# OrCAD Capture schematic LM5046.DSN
size Custom; title: LM5046 Simulation Example; company: Phoenix Design Center, National Semiconductor; note: Model by Eric Lee, Phoenix Design Center , National Semiconductor
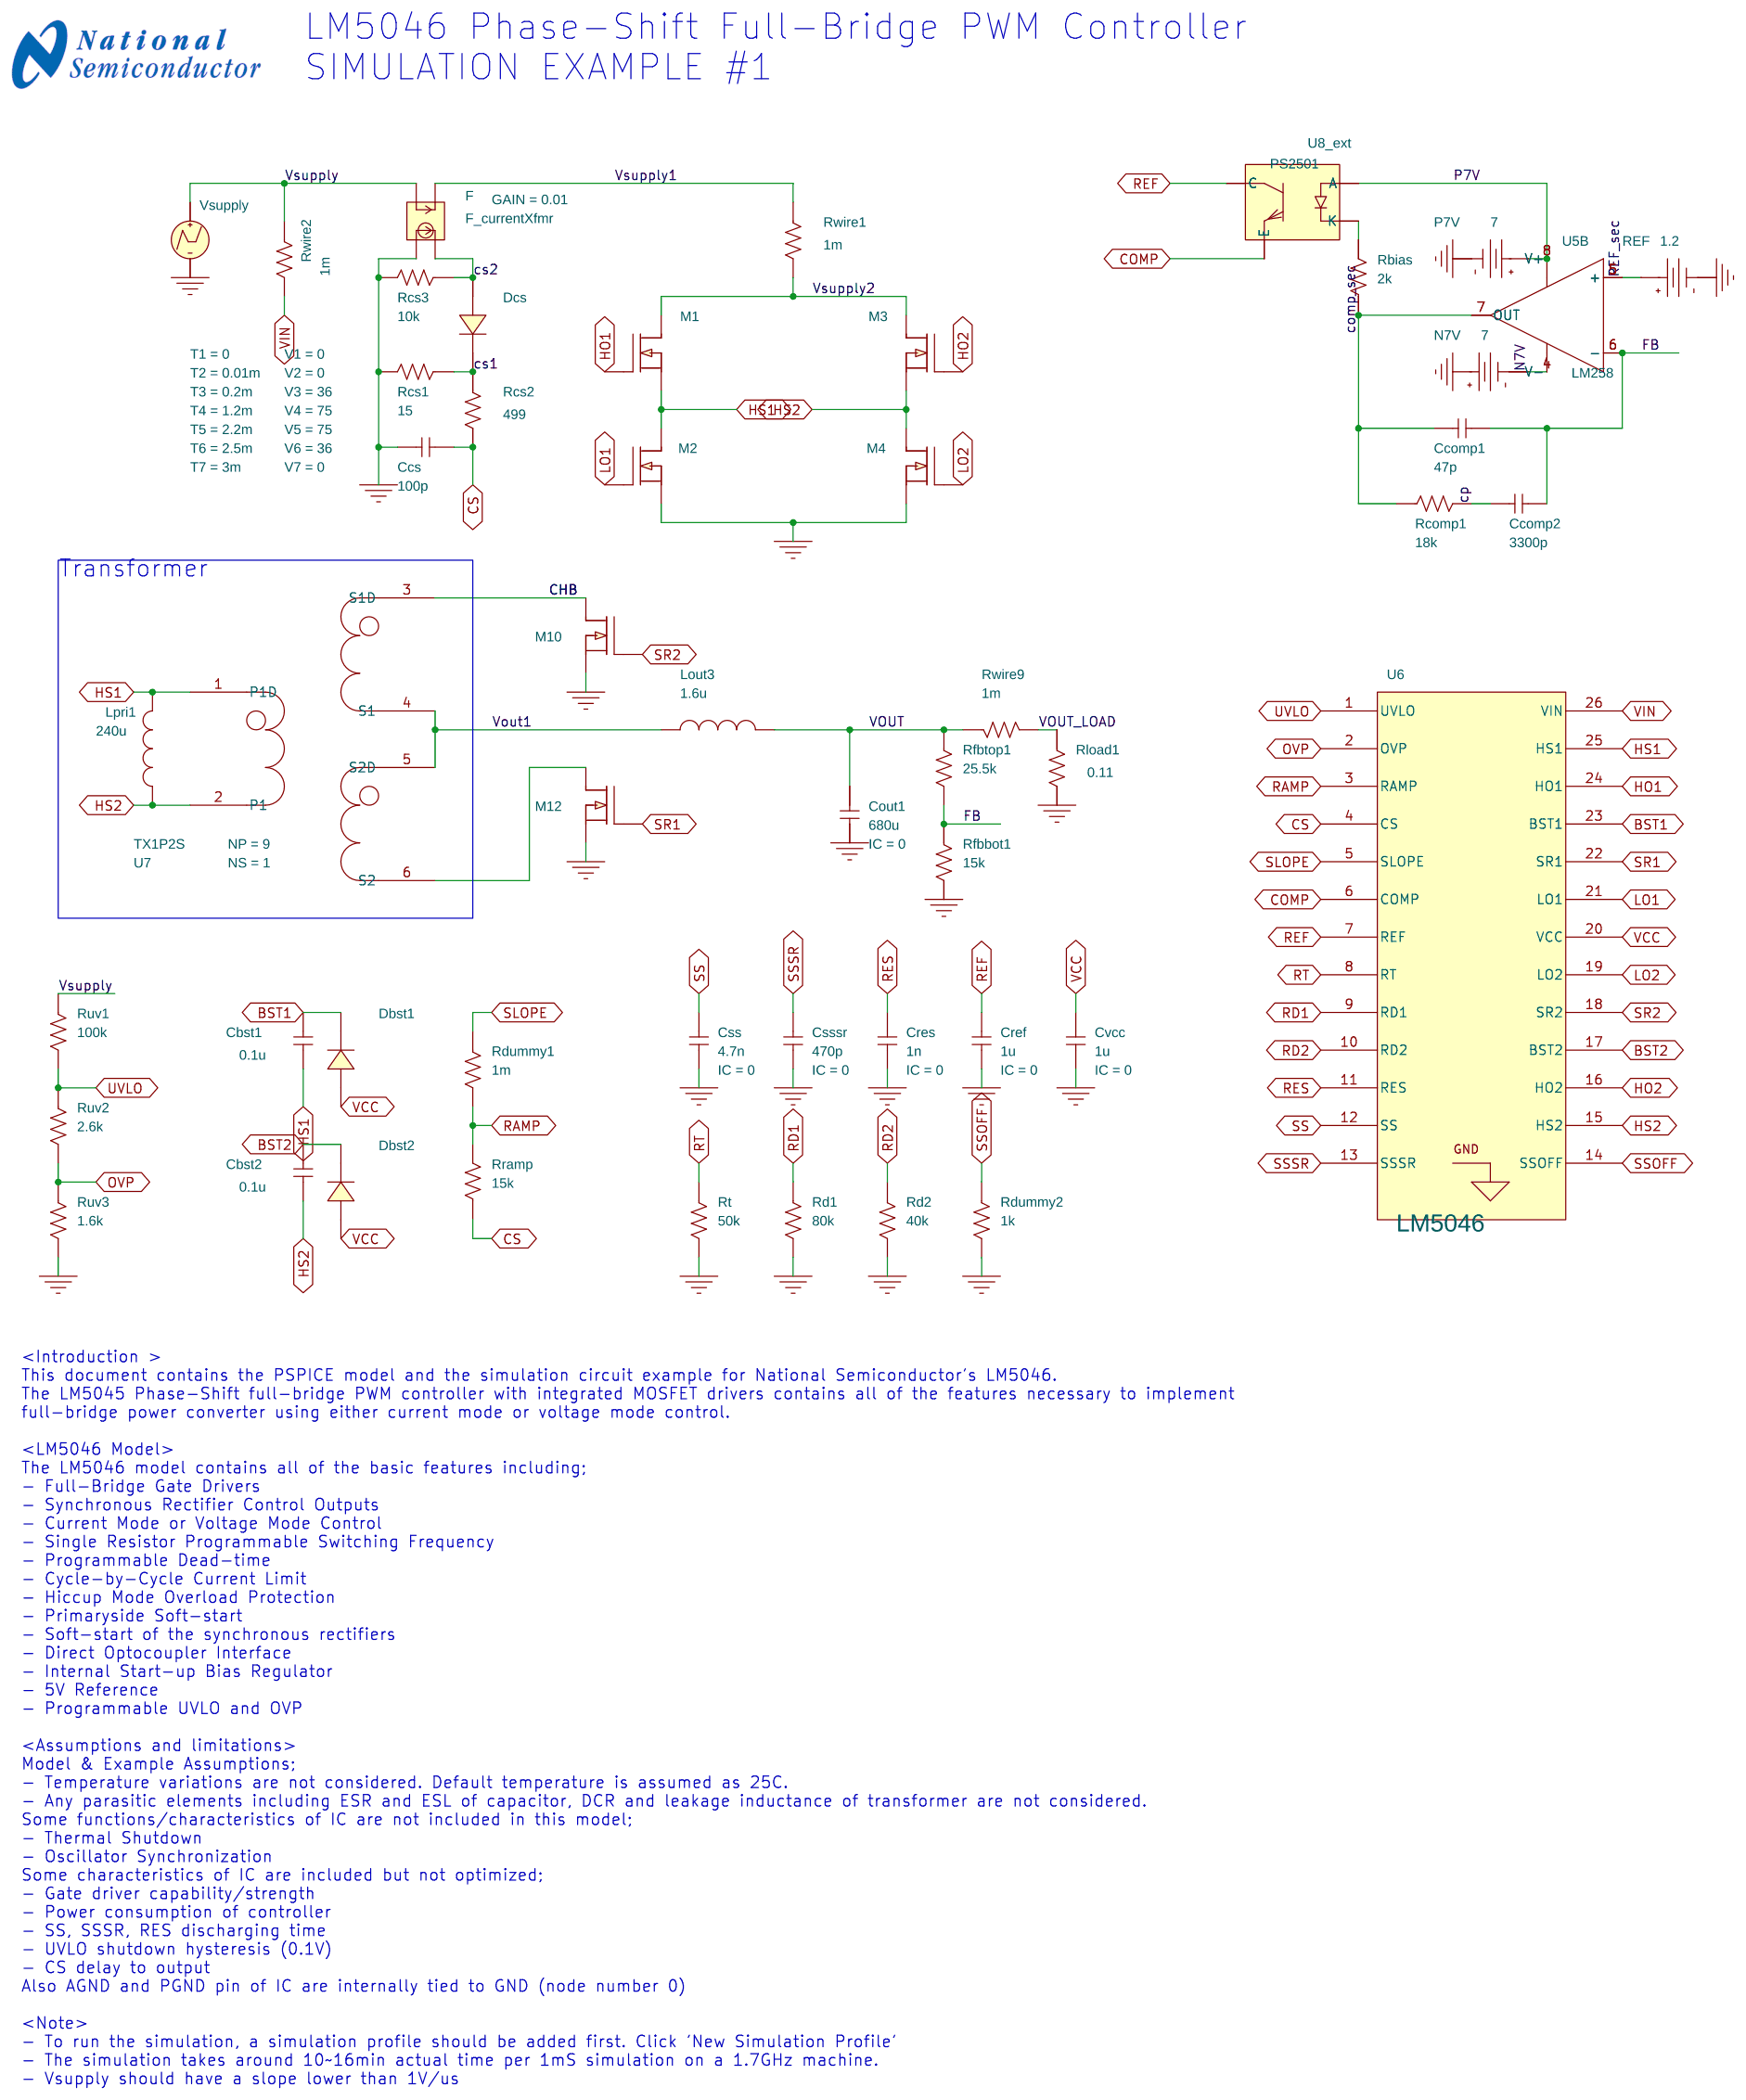
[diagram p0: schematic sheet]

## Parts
Cbst1  0.1u  [RAD/CK05]
Cbst2  0.1u  [RAD/CK05]
Ccomp1  47p  [RAD/CK05]
Ccomp2  3300p  [RAD/CK05]
Ccs  100p  [RAD/CK05]
Cout1  680u  [RAD/CK05]
Cref  1u  [RAD/CK05]
Cres  1n  [RAD/CK05]
Css  4.7n  [RAD/CK05]
Csssr  470p  [RAD/CK05]
Cvcc  1u  [RAD/CK05]
Dbst1  DNOM
Dbst2  DNOM
Dcs  DNOM
F_currentXfmr  F
Lout3  1.6u  [DISC/.350x.175/LS.200x.100/.034]
Lpri1  240u  [DISC/.350x.175/LS.200x.100/.034]
M1  NMOSNOM
M2  NMOSNOM
M3  NMOSNOM
M4  NMOSNOM
M10  NMOSNOM
M12  NMOSNOM
N7V  VDC
P7V  VDC
Rbias  2k  [AX/RC05]
Rcomp1  18k  [AX/RC05]
Rcs1  15  [AX/RC05]
Rcs2  499  [AX/RC05]
Rcs3  10k  [AX/RC05]
Rd1  80k  [AX/RC05]
Rd2  40k  [AX/RC05]
Rdummy1  1m  [AX/RC05]
Rdummy2  1k  [AX/RC05]
REF  VDC
Rfbbot1  15k  [AX/RC05]
Rfbtop1  25.5k  [AX/RC05]
Rload1  0.11  [AX/RC05]
Rramp  15k  [AX/RC05]
Rt  50k  [AX/RC05]
Ruv1  100k  [AX/RC05]
Ruv2  2.6k  [AX/RC05]
Ruv3  1.6k  [AX/RC05]
Rwire1  1m  [AX/RC05]
Rwire2  1m  [AX/RC05]
Rwire9  1m  [AX/RC05]
U5  LM258  [DIP.100/8/W.300/L.450]  (section B)
U6  LM5046
U7  TX1P2S
U8_ext  PS2501  [DIP4]
Vsupply  VPWL

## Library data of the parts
Cbst1 Cbst2 Ccomp1 Ccomp2 Ccs = C: IC: 0
Cout1 = C_2: IC: 0
Cref Cres Css Csssr Cvcc = C_3: IC: 0
Dbst1 Dbst2 Dcs = DNOM
F_currentXfmr = F: GAIN: 0.01
Lout3 Lpri1 = L
M1-M4 M10 M12 = NMOSNOM
N7V P7V = VDC: DC: 7
Rbias Rcomp1 Rcs1-Rcs3 Rd1 Rd2 Rdummy1 Rdummy2 Rfbbot1 Rfbtop1 Rload1 Rramp Rt Ruv1-Ruv3 Rwire1 Rwire2 Rwire9 = R
REF = VDC: DC: 1.2
U5 = LM258
U6 = LM5046
U7 = TX1P2S: NP: 9; NS: 1
U8_ext = PS2501-1
Vsupply = VPWL: PSpiceTemplate: V^@REFDES %+ %- ?DC|DC @DC| ?AC|AC @AC|\n+PWL @T1 @V1 @T2 @V2 #T3/@T3 @V3/ #T4/@T4 @V4/ #T5/@T5 @V5/ #T6/@T6 @V6/ #T7/@T7 @V7/ #T8/@T8 @V8/ #T9/@T9 @V9/ #T10/@T10 @V10/; T1: 0; T2: 0.01m; T3: 0.2m; T4: 1.2m; T5: 2.2m; T6: 2.5m; T7: 3m; V1: 0; V2: 0; V3: 36; V4: 75; V5: 75; V6: 36; V7: 0

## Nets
P7V: P7V.0(+) U5.8(V+) U8_ext.1(A)
VCC: Cvcc.1 Dbst1.2(A) Dbst2.2(A) U6.20(VCC)
VIN: Rwire2.2 U6.26(VIN)
0: Ccs.2 Cout1.2 Cref.2 Cres.2 Css.2 Csssr.2 Cvcc.2 F_currentXfmr.3 M2.1(s) M4.1(s) M10.1(s) M12.1(s) N7V.0(+) P7V.1(-) Rcs1.2 Rcs3.2 Rd1.2 Rd2.2 Rdummy2.2 REF.1(-) Rfbbot1.2 Rload1.2 Rt.2 Ruv3.2 Vsupply.2(-)
BST1: Cbst1.2 Dbst1.1(C) U6.23(BST1)
BST2: Cbst2.2 Dbst2.1(C) U6.17(BST2)
CHB: M10.2(d) U7.3(S1D)
COMP: U6.6(COMP) U8_ext.3(E)
comp_sec: Ccomp1.2 Rbias.1 Rcomp1.1 U5.7(OUT)
cp: Ccomp2.2 Rcomp1.2
CS: Ccs.1 Rcs2.2 Rramp.1 U6.4(CS)
cs1: Dcs.1(C) Rcs1.1 Rcs2.1
cs2: Dcs.2(A) F_currentXfmr.4 Rcs3.1
FB: Ccomp1.1 Ccomp2.1 Rfbbot1.1 Rfbtop1.2 U5.6(-)
HO1: M1.3(g) U6.24(HO1)
HO2: M3.3(g) U6.16(HO2)
HS1: Cbst1.1 Lpri1.1 M1.1(s) M2.2(d) U6.25(HS1) U7.1(P1D)
HS2: Cbst2.1 Lpri1.2 M3.1(s) M4.2(d) U6.15(HS2) U7.2(P1)
LO1: M2.3(g) U6.21(LO1)
LO2: M4.3(g) U6.19(LO2)
N7V: N7V.1(-) U5.4(V-)
OVP: Ruv2.2 Ruv3.1 U6.2(OVP)
RAMP: Rdummy1.2 Rramp.2 U6.3(RAMP)
RD1: Rd1.1 U6.9(RD1)
RD2: Rd2.1 U6.10(RD2)
REF: Cref.1 U6.7(REF) U8_ext.4(C)
REF_sec: REF.0(+) U5.5(+)
RES: Cres.1 U6.11(RES)
RT: Rt.1 U6.8(RT)
SLOPE: Rdummy1.1 U6.5(SLOPE)
SR1: M12.3(g) U6.22(SR1)
SR2: M10.3(g) U6.18(SR2)
SS: Css.1 U6.12(SS)
SSOFF: Rdummy2.1 U6.14(SSOFF)
SSSR: Csssr.1 U6.13(SSSR)
UVLO: Ruv1.2 Ruv2.1 U6.1(UVLO)
VOUT: Cout1.1 Lout3.2 Rfbtop1.1 Rwire9.1
Vout1: Lout3.1 U7.4(S1) U7.5(S2D)
VOUT_LOAD: Rload1.1 Rwire9.2
Vsupply: F_currentXfmr.1 Ruv1.1 Rwire2.1 Vsupply.1(+)
Vsupply1: F_currentXfmr.2 Rwire1.1
Vsupply2: M1.2(d) M3.2(d) Rwire1.2
N16934950: Rbias.2 U8_ext.2(K)
N16942154: M12.2(d) U7.6(S2)

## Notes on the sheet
- LM5046 Phase-Shift Full-Bridge PWM Controller
  SIMULATION EXAMPLE #1
- Transformer
- <Introduction >
  This document contains the PSPICE model and the simulation circuit example for National Semiconductor's LM5046.
  The LM5045 Phase-Shift full-bridge PWM controller with integrated MOSFET drivers contains all of the features necessary to implement
  full-bridge power converter using either current mode or voltage mode control.
  <LM5046 Model>
  The LM5046 model contains all of the basic features including;
  - Full-Bridge Gate Drivers
  - Synchronous Rectifier Control Outputs
  - Current Mode or Voltage Mode Control
  - Single Resistor Programmable Switching Frequency
  - Programmable Dead-time
  - Cycle-by-Cycle Current Limit
  - Hiccup Mode Overload Protection
  - Primaryside Soft-start
  - Soft-start of the synchronous rectifiers
  - Direct Optocoupler Interface
  - Internal Start-up Bias Regulator
  - 5V Reference
  - Programmable UVLO and OVP
  <Assumptions and limitations>
  Model & Example Assumptions;
  - Temperature variations are not considered. Default temperature is assumed as 25C.
  - Any parasitic elements including ESR and ESL of capacitor, DCR and leakage inductance of transformer are not considered.
  Some functions/characteristics of IC are not included in this model;
  - Thermal Shutdown
  - Oscillator Synchronization
  Some characteristics of IC are included but not optimized;
  - Gate driver capability/strength
  - Power consumption of controller
  - SS, SSSR, RES discharging time
  - UVLO shutdown hysteresis (0.1V)
  - CS delay to output
  Also AGND and PGND pin of IC are internally tied to GND (node number 0)
  <Note>
  - To run the simulation, a simulation profile should be added first. Click 'New Simulation Profile'
  - The simulation takes around 10~16min actual time per 1mS simulation on a 1.7GHz machine.
  - Vsupply should have a slope lower than 1V/us
